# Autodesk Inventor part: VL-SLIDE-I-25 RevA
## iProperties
Created: 2007-09
Part Number: VL-SLIDE-I-25 RevA
Material: Stainless Steel, Austenitic
Document SubType Name: Modeling
Density: 8.03 g/cm^3
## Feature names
1. Base1
